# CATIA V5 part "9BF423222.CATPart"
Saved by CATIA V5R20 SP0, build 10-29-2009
Part number: 9BF423222
Revision: ANY
Definition: UNKNOWN
Nomenclature: 9BF423222
Source: Unknown
Bounding box of the stored display mesh (mm): x -48 to -20, y -21 to 21, z 0 to 32
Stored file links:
  C:\Users\Utente\Desktop\IO LAVORO\3D X SITO CF\CUMSA\3D files SX.256062\SX 256062\9BF423222.CATPart
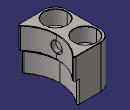
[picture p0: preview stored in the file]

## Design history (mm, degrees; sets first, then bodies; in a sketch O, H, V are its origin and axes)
Body1 "Cortar-Extruir13" (main body)
  Solid1: solid without history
